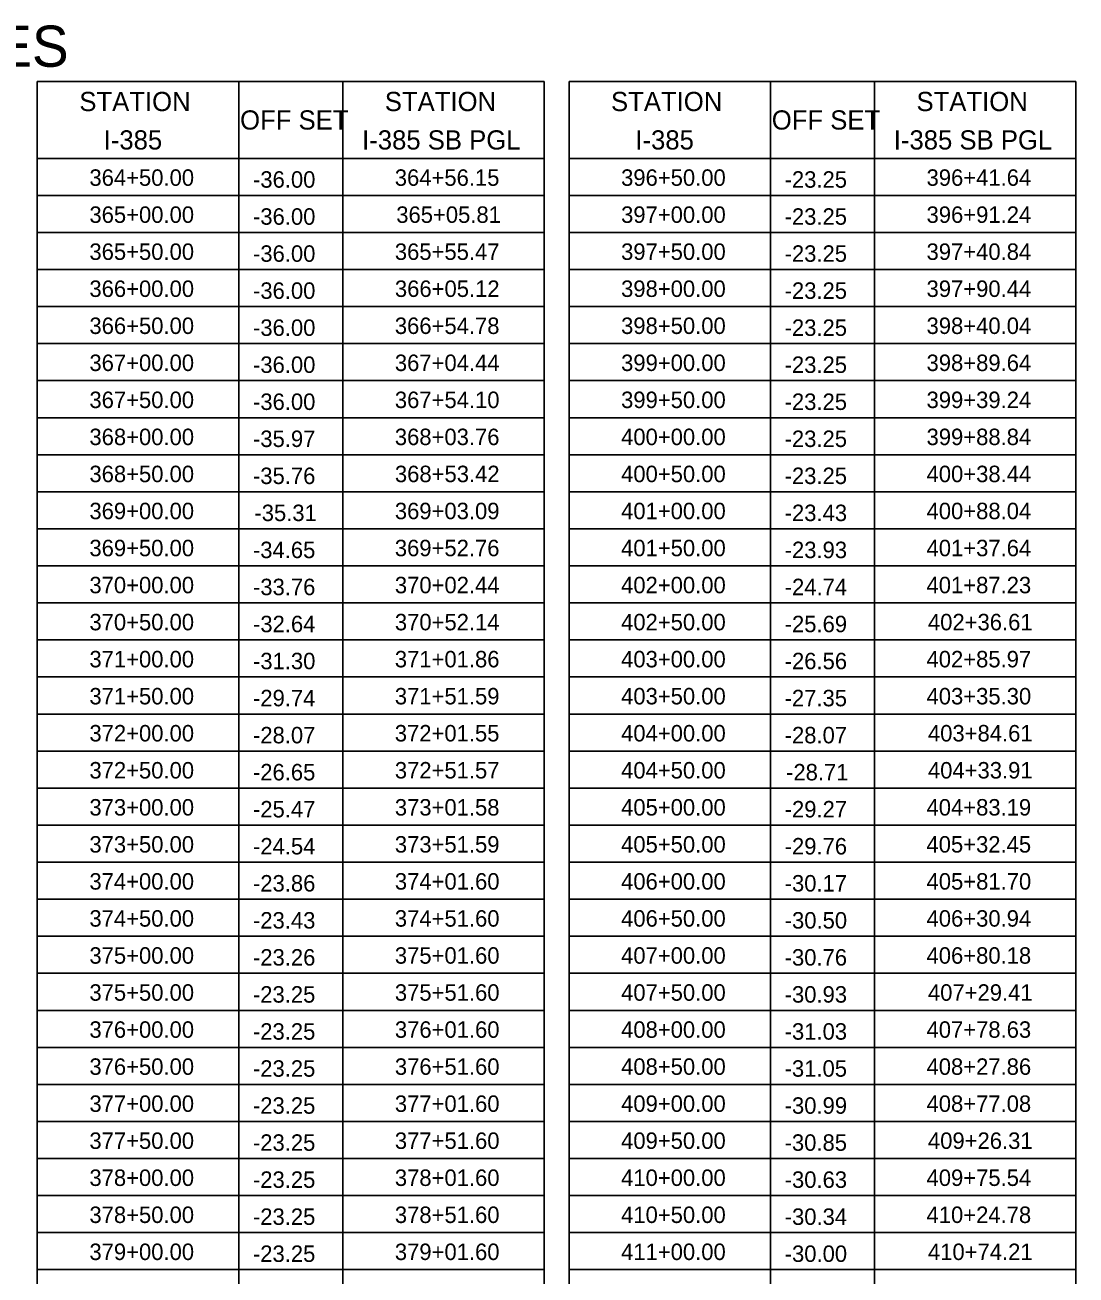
# Model space of a CAD drawing. Extents: x 1602163 to 1612907, y 1087635 to 1096265.
# Drawn here: x 1610569 to 1610952.2, y 1095754.9 to 1096210.5 of the extents above; entities that cross this region are included whole.
import ezdxf

# ---------------------------------------------------------------- set-up
doc = ezdxf.new("R2010")
doc.units = 0
doc.layers.add('RD_SHT_Misc1', color=7, linetype='Continuous')
doc.layers.add('RD_SHT_TX', color=7, linetype='Continuous')

msp = doc.modelspace()

# ---------------------------------------------------------------- linework, layer by layer
at = {"layer": 'RD_SHT_Misc1'}
for p, q in [((1610573.49, 1096189.84), (1610573.49, 1095297.84)), ((1610573.49, 1096189.84), (1610758.32, 1096189.84)), ((1610646.96, 1096189.84), (1610646.96, 1095297.84)), ((1610684.85, 1096189.84), (1610684.85, 1095297.84)), ((1610758.32, 1096189.84), (1610758.32, 1095297.84)), ((1610767.32, 1096189.84), (1610767.32, 1095297.84)), ((1610767.32, 1096189.84), (1610952.15, 1096189.84)), ((1610840.79, 1096189.84), (1610840.79, 1095297.84)), ((1610878.68, 1096189.84), (1610878.68, 1095297.84)), ((1610952.15, 1096189.84), (1610952.15, 1095297.84)), ((1610573.49, 1096161.84), (1610758.32, 1096161.84)), ((1610767.32, 1096161.84), (1610952.15, 1096161.84)), ((1610573.49, 1096148.34), (1610758.32, 1096148.34)), ((1610767.32, 1096148.34), (1610952.15, 1096148.34)), ((1610573.49, 1096134.84), (1610758.32, 1096134.84)), ((1610767.32, 1096134.84), (1610952.15, 1096134.84)), ((1610573.49, 1096121.34), (1610758.32, 1096121.34)), ((1610767.32, 1096121.34), (1610952.15, 1096121.34)), ((1610573.49, 1096107.84), (1610758.32, 1096107.84)), ((1610767.32, 1096107.84), (1610952.15, 1096107.84)), ((1610573.49, 1096094.34), (1610758.32, 1096094.34)), ((1610767.32, 1096094.34), (1610952.15, 1096094.34)), ((1610573.49, 1096080.84), (1610758.32, 1096080.84)), ((1610767.32, 1096080.84), (1610952.15, 1096080.84)), ((1610573.49, 1096067.34), (1610758.32, 1096067.34)), ((1610767.32, 1096067.34), (1610952.15, 1096067.34)), ((1610573.49, 1096053.84), (1610758.32, 1096053.84)), ((1610767.32, 1096053.84), (1610952.15, 1096053.84)), ((1610573.49, 1096040.34), (1610758.32, 1096040.34)), ((1610767.32, 1096040.34), (1610952.15, 1096040.34)), ((1610573.49, 1096026.84), (1610758.32, 1096026.84)), ((1610767.32, 1096026.84), (1610952.15, 1096026.84)), ((1610573.49, 1096013.34), (1610758.32, 1096013.34)), ((1610767.32, 1096013.34), (1610952.15, 1096013.34)), ((1610573.49, 1095999.84), (1610758.32, 1095999.84)), ((1610767.32, 1095999.84), (1610952.15, 1095999.84)), ((1610573.49, 1095986.34), (1610758.32, 1095986.34)), ((1610767.32, 1095986.34), (1610952.15, 1095986.34)), ((1610573.49, 1095972.84), (1610758.32, 1095972.84)), ((1610767.32, 1095972.84), (1610952.15, 1095972.84)), ((1610573.49, 1095959.34), (1610758.32, 1095959.34)), ((1610767.32, 1095959.34), (1610952.15, 1095959.34)), ((1610573.49, 1095945.84), (1610758.32, 1095945.84)), ((1610767.32, 1095945.84), (1610952.15, 1095945.84)), ((1610573.49, 1095932.34), (1610758.32, 1095932.34)), ((1610767.32, 1095932.34), (1610952.15, 1095932.34)), ((1610573.49, 1095918.84), (1610758.32, 1095918.84)), ((1610767.32, 1095918.84), (1610952.15, 1095918.84)), ((1610573.49, 1095905.34), (1610758.32, 1095905.34)), ((1610767.32, 1095905.34), (1610952.15, 1095905.34)), ((1610573.49, 1095891.84), (1610758.32, 1095891.84)), ((1610767.32, 1095891.84), (1610952.15, 1095891.84)), ((1610573.49, 1095878.34), (1610758.32, 1095878.34)), ((1610767.32, 1095878.34), (1610952.15, 1095878.34)), ((1610573.49, 1095864.84), (1610758.32, 1095864.84)), ((1610767.32, 1095864.84), (1610952.15, 1095864.84)), ((1610573.49, 1095851.34), (1610758.32, 1095851.34)), ((1610767.32, 1095851.34), (1610952.15, 1095851.34)), ((1610573.49, 1095837.84), (1610758.32, 1095837.84)), ((1610767.32, 1095837.84), (1610952.15, 1095837.84)), ((1610573.49, 1095824.34), (1610758.32, 1095824.34)), ((1610767.32, 1095824.34), (1610952.15, 1095824.34)), ((1610573.49, 1095810.84), (1610758.32, 1095810.84)), ((1610767.32, 1095810.84), (1610952.15, 1095810.84)), ((1610573.49, 1095797.34), (1610758.32, 1095797.34)), ((1610767.32, 1095797.34), (1610952.15, 1095797.34)), ((1610573.49, 1095783.84), (1610758.32, 1095783.84)), ((1610767.32, 1095783.84), (1610952.15, 1095783.84)), ((1610573.49, 1095770.34), (1610758.32, 1095770.34)), ((1610767.32, 1095770.34), (1610952.15, 1095770.34)), ((1610573.49, 1095756.84), (1610758.32, 1095756.84)), ((1610767.32, 1095756.84), (1610952.15, 1095756.84))]:
    msp.add_line(p, q, dxfattribs=at)

# ---------------------------------------------------------------- texts
at = {"layer": 'RD_SHT_TX'}
for s, height, p in [('I-385 TO PGL STATION AND OFF SET TABLES', 15, (1610146.87, 1096195.23)), ('STATION', 7, (1610588.81, 1096179.07)), ('STATION', 7, (1610700.17, 1096179.07)), ('STATION', 7, (1610782.64, 1096179.07)), ('STATION', 7, (1610894, 1096179.07)), ('OFF SET', 7, (1610647.41, 1096172.34)), ('OFF SET', 7, (1610841.24, 1096172.34)), ('I-385', 7, (1610597.68, 1096165.07)), ('I-385 SB PGL', 7, (1610691.89, 1096165.07)), ('I-385', 7, (1610791.51, 1096165.07)), ('I-385 SB PGL', 7, (1610885.72, 1096165.07)), ('364+50.00', 6, (1610592.48, 1096151.84)), ('364+56.15', 6, (1610703.81, 1096151.84)), ('396+50.00', 6, (1610786.31, 1096151.84)), ('396+41.64', 6, (1610897.67, 1096151.84)), ('-36.00', 6, (1610652.12, 1096151.15)), ('-23.25', 6, (1610845.92, 1096151.15)), ('365+00.00', 6, (1610592.48, 1096138.34)), ('365+05.81', 6, (1610704.35, 1096138.34)), ('397+00.00', 6, (1610786.31, 1096138.34)), ('396+91.24', 6, (1610897.67, 1096138.34)), ('-36.00', 6, (1610652.12, 1096137.65)), ('-23.25', 6, (1610845.92, 1096137.65)), ('365+50.00', 6, (1610592.48, 1096124.84)), ('365+55.47', 6, (1610703.83, 1096124.84)), ('397+50.00', 6, (1610786.31, 1096124.84)), ('397+40.84', 6, (1610897.67, 1096124.84)), ('-36.00', 6, (1610652.12, 1096124.15)), ('-23.25', 6, (1610845.92, 1096124.15)), ('366+00.00', 6, (1610592.48, 1096111.34)), ('-36.00', 6, (1610652.12, 1096110.65)), ('366+05.12', 6, (1610703.86, 1096111.34)), ('398+00.00', 6, (1610786.31, 1096111.34)), ('-23.25', 6, (1610845.92, 1096110.65)), ('397+90.44', 6, (1610897.67, 1096111.34)), ('366+50.00', 6, (1610592.48, 1096097.84)), ('-36.00', 6, (1610652.12, 1096097.15)), ('366+54.78', 6, (1610703.83, 1096097.84)), ('398+50.00', 6, (1610786.31, 1096097.84)), ('-23.25', 6, (1610845.92, 1096097.15)), ('398+40.04', 6, (1610897.67, 1096097.84)), ('367+00.00', 6, (1610592.48, 1096084.34)), ('-36.00', 6, (1610652.12, 1096083.65)), ('367+04.44', 6, (1610703.84, 1096084.34)), ('399+00.00', 6, (1610786.31, 1096084.34)), ('-23.25', 6, (1610845.92, 1096083.65)), ('398+89.64', 6, (1610897.67, 1096084.34)), ('367+50.00', 6, (1610592.48, 1096070.84)), ('-36.00', 6, (1610652.12, 1096070.15)), ('367+54.10', 6, (1610703.84, 1096070.84)), ('399+50.00', 6, (1610786.31, 1096070.84)), ('-23.25', 6, (1610845.92, 1096070.15)), ('399+39.24', 6, (1610897.67, 1096070.84)), ('368+00.00', 6, (1610592.48, 1096057.34)), ('-35.97', 6, (1610652.11, 1096056.65)), ('368+03.76', 6, (1610703.83, 1096057.34)), ('400+00.00', 6, (1610786.31, 1096057.34)), ('-23.25', 6, (1610845.92, 1096056.65)), ('399+88.84', 6, (1610897.67, 1096057.34)), ('368+50.00', 6, (1610592.48, 1096043.84)), ('-35.76', 6, (1610652.11, 1096043.15)), ('368+53.42', 6, (1610703.86, 1096043.84)), ('400+50.00', 6, (1610786.31, 1096043.84)), ('-23.25', 6, (1610845.92, 1096043.15)), ('400+38.44', 6, (1610897.67, 1096043.84)), ('369+00.00', 6, (1610592.48, 1096030.34)), ('-35.31', 6, (1610652.63, 1096029.65)), ('369+03.09', 6, (1610703.83, 1096030.34)), ('401+00.00', 6, (1610786.31, 1096030.34)), ('-23.43', 6, (1610845.94, 1096029.65)), ('400+88.04', 6, (1610897.67, 1096030.34)), ('369+50.00', 6, (1610592.48, 1096016.84)), ('-34.65', 6, (1610652.09, 1096016.15)), ('369+52.76', 6, (1610703.83, 1096016.84)), ('401+50.00', 6, (1610786.31, 1096016.84)), ('-23.93', 6, (1610845.94, 1096016.15)), ('401+37.64', 6, (1610897.67, 1096016.84)), ('370+00.00', 6, (1610592.48, 1096003.34)), ('-33.76', 6, (1610652.11, 1096002.65)), ('370+02.44', 6, (1610703.84, 1096003.34)), ('402+00.00', 6, (1610786.31, 1096003.34)), ('-24.74', 6, (1610845.95, 1096002.65)), ('401+87.23', 6, (1610897.66, 1096003.34)), ('370+50.00', 6, (1610592.48, 1095989.84)), ('-32.64', 6, (1610652.12, 1095989.15)), ('370+52.14', 6, (1610703.84, 1095989.84)), ('402+50.00', 6, (1610786.31, 1095989.84)), ('-25.69', 6, (1610845.94, 1095989.15)), ('402+36.61', 6, (1610898.18, 1095989.84)), ('371+00.00', 6, (1610592.48, 1095976.34)), ('-31.30', 6, (1610652.12, 1095975.65)), ('371+01.86', 6, (1610703.83, 1095976.34)), ('403+00.00', 6, (1610786.31, 1095976.34)), ('-26.56', 6, (1610845.94, 1095975.65)), ('402+85.97', 6, (1610897.66, 1095976.34)), ('371+50.00', 6, (1610592.48, 1095962.84)), ('-29.74', 6, (1610652.12, 1095962.15)), ('371+51.59', 6, (1610703.83, 1095962.84)), ('403+50.00', 6, (1610786.31, 1095962.84)), ('-27.35', 6, (1610845.92, 1095962.15)), ('403+35.30', 6, (1610897.67, 1095962.84)), ('372+00.00', 6, (1610592.48, 1095949.34)), ('-28.07', 6, (1610652.11, 1095948.65)), ('372+01.55', 6, (1610703.81, 1095949.34)), ('404+00.00', 6, (1610786.31, 1095949.34)), ('-28.07', 6, (1610845.94, 1095948.65)), ('403+84.61', 6, (1610898.18, 1095949.34)), ('372+50.00', 6, (1610592.48, 1095935.84)), ('-26.65', 6, (1610652.09, 1095935.15)), ('372+51.57', 6, (1610703.83, 1095935.84)), ('404+50.00', 6, (1610786.31, 1095935.84)), ('-28.71', 6, (1610846.46, 1095935.15)), ('404+33.91', 6, (1610898.18, 1095935.84)), ('373+00.00', 6, (1610592.48, 1095922.34)), ('-25.47', 6, (1610652.11, 1095921.65)), ('373+01.58', 6, (1610703.83, 1095922.34)), ('405+00.00', 6, (1610786.31, 1095922.34)), ('-29.27', 6, (1610845.94, 1095921.65)), ('404+83.19', 6, (1610897.66, 1095922.34)), ('373+50.00', 6, (1610592.48, 1095908.84)), ('-24.54', 6, (1610652.12, 1095908.15)), ('373+51.59', 6, (1610703.83, 1095908.84)), ('405+50.00', 6, (1610786.31, 1095908.84)), ('-29.76', 6, (1610845.94, 1095908.15)), ('405+32.45', 6, (1610897.64, 1095908.84)), ('374+00.00', 6, (1610592.48, 1095895.34)), ('-23.86', 6, (1610652.11, 1095894.65)), ('374+01.60', 6, (1610703.84, 1095895.34)), ('406+00.00', 6, (1610786.31, 1095895.34)), ('-30.17', 6, (1610845.94, 1095894.65)), ('405+81.70', 6, (1610897.67, 1095895.34)), ('374+50.00', 6, (1610592.48, 1095881.84)), ('-23.43', 6, (1610652.11, 1095881.15)), ('374+51.60', 6, (1610703.84, 1095881.84)), ('406+50.00', 6, (1610786.31, 1095881.84)), ('-30.50', 6, (1610845.95, 1095881.15)), ('406+30.94', 6, (1610897.67, 1095881.84)), ('375+00.00', 6, (1610592.48, 1095868.34)), ('-23.26', 6, (1610652.11, 1095867.65)), ('375+01.60', 6, (1610703.84, 1095868.34)), ('407+00.00', 6, (1610786.31, 1095868.34)), ('-30.76', 6, (1610845.94, 1095867.65)), ('406+80.18', 6, (1610897.66, 1095868.34)), ('375+50.00', 6, (1610592.48, 1095854.84)), ('-23.25', 6, (1610652.09, 1095854.15)), ('375+51.60', 6, (1610703.84, 1095854.84)), ('407+50.00', 6, (1610786.31, 1095854.84)), ('-30.93', 6, (1610845.94, 1095854.15)), ('407+29.41', 6, (1610898.18, 1095854.84)), ('376+00.00', 6, (1610592.48, 1095841.34)), ('-23.25', 6, (1610652.09, 1095840.65)), ('376+01.60', 6, (1610703.84, 1095841.34)), ('408+00.00', 6, (1610786.31, 1095841.34)), ('-31.03', 6, (1610845.94, 1095840.65)), ('407+78.63', 6, (1610897.66, 1095841.34)), ('376+50.00', 6, (1610592.48, 1095827.84)), ('-23.25', 6, (1610652.09, 1095827.15)), ('376+51.60', 6, (1610703.84, 1095827.84)), ('408+50.00', 6, (1610786.31, 1095827.84)), ('-31.05', 6, (1610845.92, 1095827.15)), ('408+27.86', 6, (1610897.66, 1095827.84)), ('377+00.00', 6, (1610592.48, 1095814.34)), ('-23.25', 6, (1610652.09, 1095813.65)), ('377+01.60', 6, (1610703.84, 1095814.34)), ('409+00.00', 6, (1610786.31, 1095814.34)), ('-30.99', 6, (1610845.94, 1095813.65)), ('408+77.08', 6, (1610897.66, 1095814.34)), ('377+50.00', 6, (1610592.48, 1095800.84)), ('-23.25', 6, (1610652.09, 1095800.15)), ('377+51.60', 6, (1610703.84, 1095800.84)), ('409+50.00', 6, (1610786.31, 1095800.84)), ('-30.85', 6, (1610845.92, 1095800.15)), ('409+26.31', 6, (1610898.18, 1095800.84)), ('378+00.00', 6, (1610592.48, 1095787.34)), ('378+01.60', 6, (1610703.84, 1095787.34)), ('410+00.00', 6, (1610786.31, 1095787.34)), ('409+75.54', 6, (1610897.67, 1095787.34)), ('-23.25', 6, (1610652.09, 1095786.65)), ('-30.63', 6, (1610845.94, 1095786.65)), ('378+50.00', 6, (1610592.48, 1095773.84)), ('378+51.60', 6, (1610703.84, 1095773.84)), ('410+50.00', 6, (1610786.31, 1095773.84)), ('410+24.78', 6, (1610897.66, 1095773.84)), ('-23.25', 6, (1610652.09, 1095773.15)), ('-30.34', 6, (1610845.95, 1095773.15)), ('379+00.00', 6, (1610592.48, 1095760.34)), ('379+01.60', 6, (1610703.84, 1095760.34)), ('411+00.00', 6, (1610786.31, 1095760.34)), ('410+74.21', 6, (1610898.18, 1095760.34)), ('-23.25', 6, (1610652.09, 1095759.65)), ('-30.00', 6, (1610845.95, 1095759.65))]:
    msp.add_text(s, height=height, dxfattribs=at).set_placement(p)

doc.saveas('drawing.dxf')
